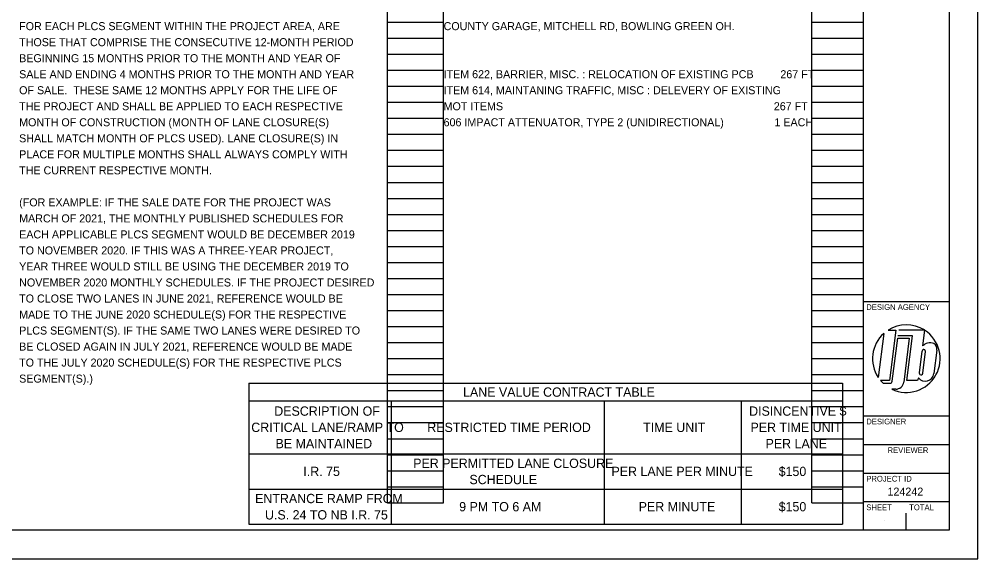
# Model space of a CAD drawing. Extents: x -53 to 237, y -2 to 24.
# Drawn here: x -36.25 to -19.49, y 1.66 to 11.09 of the extents above; entities that cross this region are included whole.
import ezdxf

# ---------------------------------------------------------------- set-up
doc = ezdxf.new("R2010")
doc.units = 0
for name, color, linetype in [('SH_Text', 7, 'Continuous'), ('SN_P_Signs', 7, 'Continuous'), ('SN_X_Text', 7, 'Continuous')]:
    doc.layers.add(name, color=color, linetype=linetype)

msp = doc.modelspace()

# ---------------------------------------------------------------- linework, layer by layer
at = {"layer": 'SH_Text'}
for p, q in [((-29.814, 2.643), (-29.814, 22.803)), ((-28.834, 2.643), (-28.834, 22.803)), ((-22.394, 2.643), (-22.394, 22.803)), ((-21.494, 2.643), (-21.494, 22.803)), ((-29.814, 11.043), (-28.834, 11.043)), ((-22.394, 11.043), (-21.494, 11.043)), ((-29.814, 10.763), (-28.834, 10.763)), ((-22.394, 10.763), (-21.494, 10.763)), ((-29.814, 10.483), (-28.834, 10.483)), ((-22.394, 10.483), (-21.494, 10.483)), ((-29.814, 10.203), (-28.834, 10.203)), ((-22.394, 10.203), (-21.494, 10.203)), ((-29.814, 9.923), (-28.834, 9.923)), ((-22.394, 9.923), (-21.494, 9.923)), ((-29.814, 9.643), (-28.834, 9.643)), ((-22.394, 9.643), (-21.494, 9.643)), ((-29.814, 9.363), (-28.834, 9.363)), ((-22.394, 9.363), (-21.494, 9.363)), ((-29.814, 9.083), (-28.834, 9.083)), ((-22.394, 9.083), (-21.494, 9.083)), ((-29.814, 8.803), (-28.834, 8.803)), ((-22.394, 8.803), (-21.494, 8.803)), ((-29.814, 8.523), (-28.834, 8.523)), ((-22.394, 8.523), (-21.494, 8.523)), ((-29.814, 8.243), (-28.834, 8.243)), ((-22.394, 8.243), (-21.494, 8.243)), ((-29.814, 7.963), (-28.834, 7.963)), ((-22.394, 7.963), (-21.494, 7.963)), ((-29.814, 7.683), (-28.834, 7.683)), ((-22.394, 7.683), (-21.494, 7.683)), ((-29.814, 7.403), (-28.834, 7.403)), ((-22.394, 7.403), (-21.494, 7.403)), ((-29.814, 7.123), (-28.834, 7.123)), ((-22.394, 7.123), (-21.494, 7.123)), ((-29.814, 6.843), (-28.834, 6.843)), ((-22.394, 6.843), (-21.494, 6.843)), ((-29.814, 6.563), (-28.834, 6.563)), ((-22.394, 6.563), (-21.494, 6.563)), ((-29.814, 6.283), (-28.834, 6.283)), ((-22.394, 6.283), (-21.494, 6.283)), ((-29.814, 6.003), (-28.834, 6.003)), ((-22.394, 6.003), (-21.494, 6.003)), ((-29.814, 5.723), (-28.834, 5.723)), ((-22.394, 5.723), (-21.494, 5.723)), ((-29.814, 5.443), (-28.834, 5.443)), ((-22.394, 5.443), (-21.494, 5.443)), ((-29.814, 5.163), (-28.834, 5.163)), ((-22.394, 5.163), (-21.494, 5.163)), ((-29.814, 4.883), (-28.834, 4.883)), ((-22.394, 4.883), (-21.494, 4.883)), ((-29.814, 4.603), (-28.834, 4.603)), ((-22.394, 4.603), (-21.494, 4.603)), ((-29.814, 4.323), (-28.834, 4.323)), ((-22.394, 4.323), (-21.494, 4.323)), ((-29.814, 4.043), (-28.834, 4.043)), ((-22.394, 4.043), (-21.494, 4.043)), ((-29.814, 3.763), (-28.834, 3.763)), ((-22.394, 3.763), (-21.494, 3.763)), ((-29.814, 3.483), (-28.834, 3.483)), ((-22.394, 3.483), (-21.494, 3.483)), ((-29.814, 3.203), (-28.834, 3.203)), ((-22.394, 3.203), (-21.494, 3.203)), ((-29.814, 2.923), (-28.834, 2.923)), ((-22.394, 2.923), (-21.494, 2.923)), ((-29.814, 2.643), (-28.834, 2.643)), ((-22.394, 2.643), (-21.494, 2.643))]:
    msp.add_line(p, q, dxfattribs=at)
at = {"layer": 'SN_P_Signs'}
for p, q in [((-32.241, 4.731), (-26.029, 4.731)), ((-32.241, 4.731), (-32.241, 2.883)), ((-26.029, 4.731), (-21.857, 4.731)), ((-21.857, 4.731), (-21.857, 2.883)), ((-32.241, 4.423), (-26.029, 4.423)), ((-29.751, 4.423), (-29.751, 2.883)), ((-26.029, 4.423), (-21.857, 4.423)), ((-26.029, 4.423), (-26.029, 2.883)), ((-23.629, 4.423), (-23.629, 2.883)), ((-32.241, 3.499), (-26.029, 3.499)), ((-26.029, 3.499), (-21.857, 3.499)), ((-32.241, 2.883), (-26.029, 2.883)), ((-32.241, 2.883), (-32.241, 2.267)), ((-29.751, 2.883), (-29.751, 2.267)), ((-26.029, 2.883), (-21.857, 2.883)), ((-26.029, 2.883), (-26.029, 2.267)), ((-23.629, 2.883), (-23.629, 2.267)), ((-21.857, 2.883), (-21.857, 2.267)), ((-32.241, 2.267), (-26.029, 2.267)), ((-26.029, 2.267), (-21.857, 2.267))]:
    msp.add_line(p, q, dxfattribs=at)
at = {"layer": 'SN_X_Text'}
for p, q in [((-21.494, 2.163), (-21.494, 23.163)), ((-21.494, 6.163), (-19.994, 6.163)), ((-21.138, 5.603), (-21.235, 4.835)), ((-21.062, 5.661), (-20.927, 5.661)), ((-20.927, 5.661), (-21.038, 4.781)), ((-20.638, 5.559), (-20.89, 5.559)), ((-20.877, 5.663), (-20.429, 5.663)), ((-20.736, 4.781), (-20.638, 5.559)), ((-20.424, 5.659), (-20.459, 5.383)), ((-20.99, 4.767), (-20.895, 5.518)), ((-20.895, 5.518), (-20.693, 5.518)), ((-20.693, 5.518), (-20.79, 4.752)), ((-20.47, 5.294), (-20.518, 4.913)), ((-20.458, 4.906), (-20.41, 5.287)), ((-20.211, 5.312), (-20.263, 4.9)), ((-20.744, 5.163), (-20.744, 5.163)), ((-21.038, 4.781), (-21.195, 4.781)), ((-21.147, 4.731), (-21.032, 4.731)), ((-20.547, 4.781), (-20.736, 4.781)), ((-20.53, 4.824), (-20.547, 4.781)), ((-20.929, 4.629), (-20.996, 4.629)), ((-21.494, 4.163), (-19.994, 4.163)), ((-21.494, 3.663), (-19.994, 3.663)), ((-21.494, 3.163), (-19.994, 3.163)), ((-21.494, 2.663), (-19.994, 2.663)), ((-20.744, 2.163), (-20.744, 2.463)), ((-21.119, 2.338), (-21.119, 2.338))]:
    msp.add_line(p, q, dxfattribs=at)
for points in [[(-53.494, 1.663), (-19.494, 1.663), (-19.494, 23.663), (-53.494, 23.663)], [(-51.994, 23.163), (-19.994, 23.163), (-19.994, 2.163), (-51.994, 2.163)]]:
    msp.add_lwpolyline(points, close=True, dxfattribs=at)
for centre, radius, start, end in [((-20.744, 5.163), 0.591, 57.726, 122.5688), ((-20.744, 5.163), 0.591, 131.8253, 213.7822), ((-20.744, 5.163), 0.591, 244.7646, 57.1575), ((-20.324, 5.249), 0.19, 105.9444, 135.0487), ((-20.33, 5.263), 0.175, 66.6782, 105.4185), ((-20.317, 5.332), 0.108, 349.2072, 58.7163), ((-20.44, 5.291), 0.0301, 352.3298, 173.2777), ((-20.413, 4.918), 0.151, 218.6264, 353.0883), ((-20.488, 4.909), 0.0301, 172.3335, 353.274), ((-20.744, 5.163), 0.591, 220.2786, 227.0158), ((-21.032, 4.773), 0.0417, 270, 352.8038), ((-20.929, 4.769), 0.141, 270, 352.8038)]:
    msp.add_arc(centre, radius, start, end, dxfattribs=at)

# ---------------------------------------------------------------- texts
at = {"layer": 'SN_P_Signs'}
for s, height, p in [('FOR EACH PLCS SEGMENT WITHIN THE PROJECT AREA, ARE', 0.14, (-36.254, 10.903)), ('COUNTY GARAGE, MITCHELL RD, BOWLING GREEN OH.', 0.14, (-28.834, 10.903)), ('THOSE THAT COMPRISE THE CONSECUTIVE 12-MONTH PERIOD', 0.14, (-36.254, 10.623)), ('BEGINNING 15 MONTHS PRIOR TO THE MONTH AND YEAR OF', 0.14, (-36.254, 10.343)), ('SALE AND ENDING 4 MONTHS PRIOR TO THE MONTH AND YEAR', 0.14, (-36.254, 10.063)), ('ITEM 622, BARRIER, MISC. : RELOCATION OF EXISTING PCB         267 FT', 0.14, (-28.834, 10.063)), ('OF SALE.  THESE SAME 12 MONTHS APPLY FOR THE LIFE OF', 0.14, (-36.254, 9.783)), ('ITEM 614, MAINTANING TRAFFIC, MISC : DELEVERY OF EXISTING', 0.14, (-28.834, 9.783)), ('THE PROJECT AND SHALL BE APPLIED TO EACH RESPECTIVE', 0.14, (-36.254, 9.503)), ('MOT ITEMS                                                                                           267 FT', 0.14, (-28.834, 9.503)), ('MONTH OF CONSTRUCTION (MONTH OF LANE CLOSURE(S)', 0.14, (-36.254, 9.223)), ('606 IMPACT ATTENUATOR, TYPE 2 (UNIDIRECTIONAL)                 1 EACH      ', 0.14, (-28.834, 9.223)), ('SHALL MATCH MONTH OF PLCS USED). LANE CLOSURE(S) IN', 0.14, (-36.254, 8.943)), ('PLACE FOR MULTIPLE MONTHS SHALL ALWAYS COMPLY WITH', 0.14, (-36.254, 8.663)), ('THE CURRENT RESPECTIVE MONTH.', 0.14, (-36.254, 8.383)), ('(FOR EXAMPLE: IF THE SALE DATE FOR THE PROJECT WAS', 0.14, (-36.254, 7.823)), ('MARCH OF 2021, THE MONTHLY PUBLISHED SCHEDULES FOR', 0.14, (-36.254, 7.543)), ('EACH APPLICABLE PLCS SEGMENT WOULD BE DECEMBER 2019', 0.14, (-36.254, 7.263)), ('TO NOVEMBER 2020. IF THIS WAS A THREE-YEAR PROJECT,', 0.14, (-36.254, 6.983)), ('YEAR THREE WOULD STILL BE USING THE DECEMBER 2019 TO', 0.14, (-36.254, 6.703)), ('NOVEMBER 2020 MONTHLY SCHEDULES. IF THE PROJECT DESIRED', 0.14, (-36.254, 6.423)), ('TO CLOSE TWO LANES IN JUNE 2021, REFERENCE WOULD BE', 0.14, (-36.254, 6.143)), ('MADE TO THE JUNE 2020 SCHEDULE(S) FOR THE RESPECTIVE', 0.14, (-36.254, 5.863)), ('PLCS SEGMENT(S). IF THE SAME TWO LANES WERE DESIRED TO', 0.14, (-36.254, 5.583)), ('BE CLOSED AGAIN IN JULY 2021, REFERENCE WOULD BE MADE', 0.14, (-36.254, 5.303)), ('TO THE JULY 2020 SCHEDULE(S) FOR THE RESPECTIVE PLCS', 0.14, (-36.254, 5.023)), ('SEGMENT(S).)', 0.14, (-36.254, 4.743)), ('LANE VALUE CONTRACT TABLE', 0.16237, (-28.494, 4.496)), ('DESCRIPTION OF ', 0.16237, (-31.794, 4.164)), ('DISINCENTIVE $ ', 0.16237, (-23.492, 4.164)), ('CRITICAL LANE/RAMP TO ', 0.16237, (-32.196, 3.88)), ('RESTRICTED TIME PERIOD', 0.16237, (-29.119, 3.88)), ('TIME UNIT', 0.1624, (-25.345, 3.88)), ('PER TIME UNIT ', 0.16237, (-23.468, 3.88)), ('BE MAINTAINED', 0.16237, (-31.772, 3.596)), ('PER LANE', 0.1624, (-23.205, 3.596)), ('PER PERMITTED LANE CLOSURE ', 0.16237, (-29.365, 3.252)), ('I.R. 75', 0.1624, (-31.286, 3.11)), ('PER LANE PER MINUTE', 0.16237, (-25.899, 3.11)), ('$150', 0.1624, (-22.976, 3.11)), ('SCHEDULE', 0.1624, (-28.382, 2.968)), ('ENTRANCE RAMP FROM ', 0.16237, (-32.129, 2.636)), ('U.S. 24 TO NB I.R. 75', 0.16237, (-31.956, 2.351)), ('9 PM TO 6 AM', 0.16237, (-28.561, 2.493)), ('PER MINUTE', 0.1624, (-25.423, 2.493)), ('$150', 0.1624, (-22.976, 2.493))]:
    msp.add_text(s, height=height, dxfattribs=at).set_placement(p)
at = {"layer": 'SN_X_Text'}
for s, height, p in [('DESIGN AGENCY', 0.1, (-21.444, 6.013)), ('DESIGNER', 0.1, (-21.444, 4.013)), ('REVIEWER', 0.1, (-21.072, 3.513)), ('PROJECT ID', 0.1, (-21.444, 3.013)), ('124242', 0.14, (-21.073, 2.768)), ('SHEET', 0.1, (-21.444, 2.513)), ('TOTAL', 0.1, (-20.694, 2.513))]:
    msp.add_text(s, height=height, dxfattribs=at).set_placement(p)

doc.saveas('drawing.dxf')
